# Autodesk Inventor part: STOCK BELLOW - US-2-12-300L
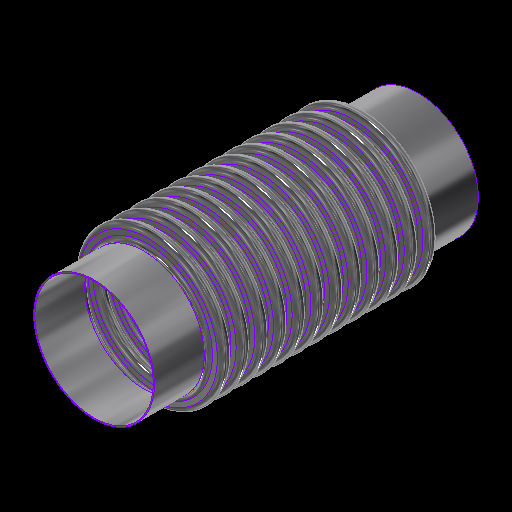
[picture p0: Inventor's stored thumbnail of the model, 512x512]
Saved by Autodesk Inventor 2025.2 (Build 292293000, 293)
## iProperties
Category: 24 GA (0.024 THICK)
RuleStatus: InUse
Created: 2024-01
Part Number: STOCK BELLOW - US-2-12-300L
Project: =STOCK BELLOWS: <Stock Number><SFILL>
Material: ASTM A240-304
Description: =STOCK BELLOWS: <Stock Number>, <SID_> I.D., <SOD_> O.D., <SPLY_> PLY, <Category>, <SNET_CONS> CONS.<PITCH_><STANGENT_> TANGENT<SFILL>
Document SubType Name: Sheet Metal
Designer: GS
Stock Number: U.S-2-12-300L
Surface Area: 1235.64 cm^2
Volume: 37.4488 cm^3
Sheet Metal Rule: Default
Appearance: STAINLESS STEEL
Mass: 301.736 g
Density: 8.05729 g/cm^3
THK: 0.036
ID: 3.500
OD: 4.250
CONS_: 2
PITCH: 0.500
TANGENT: 0.500
BELLOWS_UPSET: 0.000
d79: 1.000
d82: 1.000
d83: 26.000
d84: 24.000
d174: 8
d214: 8
STHK_: 0.024
SID_: 2.375
SOD_: 3.000
SPITCH_: 0.375
STANGENT__: 1.000
SBELLOWS_UPSET_: 0.000
SDIFF_TAN: 1.000
d252: 2
d275: 2
d287: 0.050
d289: 0.500
d290: 0.000
SOD_NECK: 2 7/16
PLY: 1
PSET: 4.178
PBAR: 1.035
COUNTER: 1.500
NET_TUBE: 3.071
CONS: 2
S_CONS: 0
NET_CONS: 2
ID_M: 88.90 mm
OD_M: 107.95 mm
THK_M: 0.91 mm
ID_U: 3.500 in
OD_U: 4.250 in
THK_U: 0.036 in
TANGENT2: 0.500
TAN_TO_TAN: 1.000 in
d80: 2.571
d81: 10
SID: 2.375
SCONS_: 12
SPITCH: 0.250
STANGENT_: 1.000
SBELLOWS_UPSET: 0.000
SNET_CONS: 12
SS_CONS: 0
SCONS: 8
d190: 8
d191: 1
d192: 1
d193: 8
d194: 0
SIZE: 2.00
PRESSURE: 300
d230: 8
STANGENT: 4.000
SPLY_: 1
d233: 8
d234: 0
d263: 2
d265: 1
d268: 2
d269: 0
d286: 2
d288: 1
d291: 2
d292: 0
SREROLL: 0.750
BLETP: 1.000 ul
PRES_Copy: 85
MATTABLE: 20 GA (0.036 THICK)
PART_NUMBER: U.S-2-12-300L
PITCH_: =, <SPITCH_> PITCH,
CFILL: .
SFILL: .
MESH: ,
COMP: 0.48
EXT: 0.24
LAT: 0.27
ANG: 573
ASR: 693
LSR: 462
ANSR: 14
PRES: 300
COMPM: 4.8
EXTM: 2.4
LATM: 2.70
ASRM: 121.365
PRESM: 20.684
LSRM: 80.910
ANSRM: 2.452
TEMPMIN: 20
TEMPMAX: 800
TEMPMINM: -7
TEMPMAXM: 427
WEIGHTM: 0.302
WEIGHT: 0.665
Author: GS
Keywords: 20 GA (0.036 THICK)
Comments: =STOCK BELLOW - <STOCK NUMBER>
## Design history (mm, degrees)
sketch "Sketch2"
  geometry: L1 (0, -177.245)-(0, 562.856) reference; L2 (45.364, 0)-(44.45, 0); L3 (48.082, -2.718)-(50.343, -2.718); L4 (48.082, -3.632)-(50.343, -3.632); L5 (50.343, -9.982)-(48.082, -9.982); L6 (50.343, -9.068)-(48.082, -9.068); L7 (45.364, -12.7)-(44.45, -12.7); L8 (48.082, 0)-(48.082, -12.7); L9 (50.343, -6.35)-(53.975, -6.35); L10 (44.45, 0)-(44.45, -12.7); L11 (20.376, 102.841)-(20.376, 101.926); L12 (58.262, 457.127)-(58.262, 349.177); L13 (58.262, 444.427)-(58.262, 336.477); L14 (93.133, -58.817)-(93.133, -71.517); L15 (118.746, -66.401)-(118.746, -66.401); L16 (50.343, -9.068)-(50.343, -9.982); L17 (48.082, -9.068)-(48.082, -9.982); L18 (48.082, -9.525)-(50.343, -9.525); L19 (53.975, 0)-(53.975, -12.7); L20 (-50.343, -9.068)-(-50.343, -9.982); L21 (-50.343, -2.718)-(-48.082, -2.718); L22 (-50.343, -3.632)-(-48.082, -3.632); L23 (-48.082, -9.068)-(-50.343, -9.068); L24 (-50.343, -9.525)-(-48.082, -9.525); L25 (-48.082, -9.982)-(-50.343, -9.982); L26 (-48.082, -9.068)-(-48.082, -9.982); L27 (-44.45, 0.653)-(-44.45, -12.047); L28 (-48.082, -6.35)-(-44.45, -6.35); L29 (-50.343, 0.653)-(-50.343, -12.7); L30 (-53.061, 0)-(-53.975, 0); L31 (-53.975, 0)-(-53.975, -12.7); L32 (-53.061, -12.7)-(-53.975, -12.7); A1 r 2.718 centre (48.082, 0) between (45.364, 0) and (48.082, -2.718); A2 r 3.632 centre (48.082, 0) between (44.45, 0) and (48.082, -3.632); A3 r 3.632 centre (50.343, -6.35) between (50.343, -9.982) and (50.343, -2.718); A4 r 2.718 centre (50.343, -6.35) between (50.343, -9.068) and (50.343, -3.632); A5 r 2.718 centre (48.082, -12.7) between (48.082, -9.982) and (45.364, -12.7); A6 r 3.632 centre (48.082, -12.7) between (48.082, -9.068) and (44.45, -12.7); A7 r 3.175 centre (50.343, -6.35) between (50.343, -9.525) and (53.518, -6.35); A8 r 3.175 centre (48.082, -12.7) between (48.082, -9.525) and (44.907, -12.7); A9 r 2.718 centre (-50.343, -12.7) between (-50.343, -9.982) and (-53.061, -12.7); A10 r 2.718 centre (-48.082, -6.35) between (-48.082, -9.068) and (-48.082, -3.632); A11 r 3.175 centre (-48.082, -6.35) between (-48.082, -9.525) and (-44.907, -6.35); A12 r 3.632 centre (-48.082, -6.35) between (-48.082, -9.982) and (-48.082, -2.718); A13 r 3.175 centre (-50.343, -12.7) between (-50.343, -9.525) and (-53.518, -12.7); A14 r 3.632 centre (-50.343, -12.7) between (-50.343, -9.068) and (-53.975, -12.7); A15 r 2.718 centre (-50.343, 0) between (-53.061, 0) and (-50.343, -2.718); A16 r 3.632 centre (-50.343, 0) between (-53.975, 0) and (-50.343, -3.632); 10 further points
  constraints: 62 end point, 38 point on circle, 20 tangent, 16 centre point, 12 parallel, 9 midpoint, 7 vertical, 6 coincident, 6 concentric, 6 point on line, 4 equal radius, 4 perpendicular, 3 horizontal, 1 collinear, 1 horizontal alignment, 10 other
  dimensions: "THK" = 0.9144 distance of L11.start L11.end; "ID" = 88.9 distance of L11.end point (20.376, 13.026); "OD" = 107.95 distance of L12.start L12.end; "PITCH" = 12.7 distance of L12.start L13.start; "TANGENT" = 12.7 distance of L14.start L14.end; "BELLOWS_UPSET" = 0 distance of L15.start L15.end; "d43" = 88.9 diameter of L10 L1 (= ID); "d44" = 107.95 diameter of L9.end L1 (= OD); "d45" = 0.9144 distance between parallel lines of L5 L6 (computed from THK, PLY); "d46" = 3.6322 radius of A3 (computed from PITCH, THK, PLY); "UPSET_PITCH" = 12.7 distance of L2.end L7.end (derived); "SIDEWALL_ANGLE" = 360 deg dimension on L3 L9 (derived); "CON_GAP" = 5.4356 distance of point (48.082, -9.068) point (48.082, -3.632) (derived); "TAN1" = 4.98728 dimension on A8 (derived); "TAN2" = 4.98728 dimension on A7 (derived); "LEG1" = 2.2606 distance of L18.start L18.end (derived); "d278" = 0.9144 distance between parallel lines of L25 L23 (derived); "d279" = 3.6322 radius of A12 (derived); "d280" = 12.7 distance of L30.end L31.end (derived); "d281" = 360 deg dimension on L21 L28 (derived); "d282" = 5.4356 distance of point (-50.343, -9.068) point (-50.343, -3.632) (derived); "d283" = 4.98728 dimension on A13 (derived); "d284" = 4.98728 dimension on A11 (derived); "d285" = 2.2606 distance of L24.start L24.end (derived); "d293" = 88.9 diameter of L27 L1 (derived); "d294" = 107.95 diameter of L31 L1 (derived)
  node "Sketch Rectangular Pattern1" dims "d31" = 25.4, "ID" = 88.9
  node "Sketch Rectangular Pattern2" dims "d39" = 25.4, "PITCH" = 12.7
revolve "CONS" stored, may be unused: angle "d48" = 90 deg
node "BELLOW MIDPLANE"
pattern_linear "Rectangular Pattern2" dims "d52" = 12.7 (= UPSET_PITCH)
sketch "Sketch5"
  geometry: C1 r 45.364 at (0, 0) reference; C2 r 44.45 at (0, 0) reference
extrude "TANGENT" new body sketch "Sketch5" distance "d53" = 12.7 (= TANGENT); taper "d54" = 0 deg
revolve "SAMETAN" stored, may be unused: angle "d65" = 90 deg
revolve "DIFFTAN" stored, may be unused: angle "d70" = 90 deg
sketch "Sketch9"
  geometry: L1 (53.319, 0)-(-53.319, 0) reference; L2 (0, -17.78)-(0, 17.78) reference; L3 (38.085, 0)-(-38.085, 0); L4 (38.085, -11.906)-(38.085, 11.906); L5 (25.385, -11.906)-(25.385, 11.906); L6 (13.15, 11.906)-(13.15, -11.906); L7 (-25.385, -11.906)-(-25.385, 11.906); L8 (-38.085, -11.906)-(-38.085, 11.906); L9 (37.291, -11.906)-(37.291, 11.906); L10 (38.085, -11.906)-(37.291, -11.906); L11 (38.085, 11.906)-(37.291, 11.906); L12 (13.546, 11.906)-(12.753, 11.906); L13 (12.753, 11.906)-(12.753, -11.906); L14 (12.753, -11.906)-(13.546, -11.906); L15 (13.546, -11.906)-(13.546, 11.906); L16 (-13.546, 11.906)-(-13.546, -11.906); L17 (-13.15, 11.906)-(-13.15, -11.906); L18 (-13.546, -11.906)-(-12.753, -11.906); L19 (-12.753, -11.906)-(-12.753, 11.906); L20 (-12.753, 11.906)-(-13.546, 11.906); L21 (-38.085, -11.906)-(-37.291, -11.906); L22 (-37.291, -11.906)-(-37.291, 11.906); L23 (-37.291, 11.906)-(-38.085, 11.906); L24 (-38.085, 11.906)-(-38.085, -11.906); L25 (38.085, -0.397)-(-38.085, -0.397); L26 (-38.085, -0.397)-(-38.085, 0.397); L27 (-38.085, 0.397)-(38.085, 0.397); L28 (38.085, 0.397)-(38.085, -0.397); L29 (-38.085, 11.906)-(38.085, 11.906); L30 (38.085, 11.906)-(38.085, 12.7); L31 (38.085, 12.7)-(-38.085, 12.7); L32 (-38.085, 12.7)-(-38.085, 11.906); L33 (38.085, -11.906)-(-38.085, -11.906); L34 (-38.085, -11.906)-(-38.085, -12.7); L35 (-38.085, -12.7)-(38.085, -12.7); L36 (38.085, -12.7)-(38.085, -11.906); 30 further points
  constraints: 68 end point, 13 midpoint, 13 parallel, 8 horizontal, 7 perpendicular, 6 equal length, 3 point on line, 2 vertical, 14 other
  dimensions: "d115" = 23.8125 distance of L4.start L4.end (derived); "d116" = 12.7 distance between parallel lines of L4 L5 (derived); "d117" = 12.23516 distance between parallel lines of L5 L6 (derived); "d125" = 38.53427 distance between parallel lines of L7 L6 (derived); "d127" = 12.7 distance between parallel lines of L8 L7 (derived); "d128" = 24.93516 distance between parallel lines of L6 L4 (derived); "d130" = 76.16943 distance between parallel lines of L8 L4 (derived); "RULER_THK" = 0.79375 distance between parallel lines of L4 L9; "d135" = 0.79375 distance of L13.end L14.end (derived); "d138" = 26.29911 distance of L13.end L16.end (derived); "d143" = 0.79375 distance of L22.end L8.end (derived); "d144" = 0.79375 distance between parallel lines of L27 L25 (derived)
extrude "RULER" join sketch "Sketch9" distance "d149" = 0.79375 (derived); taper "d150" = 0 deg
extrude "BARS" join sketch "Sketch9" distance "d151" = 0.79375 (derived); taper "d152" = 0 deg
pattern_linear "Rectangular Pattern4" dims "d155" = 26.29911 (derived)
sketch "Sketch13"
  geometry: L1 (93.149, -52.467)-(93.149, -77.867); L2 (30.772, 0)-(30.162, 0); L3 (30.772, -9.525)-(30.162, -9.525); L4 (35.414, -7.449)-(32.849, -7.449); L5 (35.414, -6.839)-(32.849, -6.839); L6 (35.414, -4.763)-(38.1, -4.762); L7 (32.849, -2.076)-(35.414, -2.076); L8 (32.849, 0)-(32.849, -9.525); L9 (30.162, 0)-(30.162, -9.525); L10 (58.254, -420.231)-(58.254, -496.431); L11 (58.254, -429.756)-(58.254, -505.956); L12 (58.254, -448.806)-(58.254, -525.006); L13 (58.254, -458.331)-(58.254, -534.531); L14 (58.254, -467.856)-(58.254, -544.056); L15 (58.254, -477.381)-(58.254, -553.581); L16 (58.254, -486.906)-(58.254, -563.106); L17 (58.254, -439.281)-(58.254, -515.481); L18 (20.376, 102.536)-(20.376, 101.926); L19 (32.849, -2.686)-(35.414, -2.686); L20 (0, -696.234)-(0, 235.664) reference; L21 (-23.752, 0)-(142.514, 0) reference; A1 r 2.076 centre (32.849, 0) between (30.772, 0) and (32.849, -2.076); A2 r 2.076 centre (32.849, -9.525) between (32.849, -7.449) and (30.772, -9.525); A3 r 2.686 centre (32.849, -9.525) between (32.849, -6.839) and (30.162, -9.525); A4 r 2.076 centre (35.414, -4.763) between (35.414, -6.839) and (35.414, -2.686); A5 r 2.686 centre (35.414, -4.763) between (35.414, -7.449) and (35.414, -2.076); A6 r 2.686 centre (32.849, 0) between (30.162, 0) and (32.849, -2.686); 6 further points; 1 other entity
  constraints: 38 end point, 15 point on circle, 9 tangent, 6 centre point, 6 parallel, 5 vertical alignment, 4 point on line, 4 vertical, 3 coincident, 3 concentric, 2 collinear, 2 equal radius, 1 horizontal, 1 perpendicular, 23 other
  dimensions: "SBELLOWS_UPSET_" = 0 distance of point (118.762, -66.401) point (118.762, -66.401); "STOTAL_THK_BELLOW__" = 0.6096 distance between parallel lines of L4 L5 (derived); "d224" = 2.68605 radius of A5 (derived); "d225" = 9.525 distance of L2.end L3.end (derived); "SSIDEWALL_ANGLE_" = 360 deg dimension on L7 L6 (derived); "SSCON_GAP_" = 4.1529 distance of point (32.849, -6.839) point (32.849, -2.686) (derived); "d235" = 60.325 diameter of L9 L20 (derived); "d236" = 76.2 diameter of L6.end L20 (derived)
  node "Sketch Rectangular Pattern4" dims "d228" = 25.4
  node "Sketch Rectangular Pattern5" dims "d229" = 25.4
revolve "SBELLOW" stored, may be unused: angle "d197" = 90 deg
pattern_linear "Rectangular Pattern5" dims "d204" = 9.525 (derived)
revolve "STANGENT" stored, may be unused: angle "d240" = 90 deg
revolve "SSAMETAN" stored, may be unused: angle "d241" = 90 deg
revolve "SDIFFTAN" stored, may be unused: angle "d246" = 90 deg
revolve "INVCON" stored, may be unused: angle "d295" = 90 deg
pattern_linear "Rectangular Pattern6" dims "d298" = 12.7 (derived)
revolve "INVTANGENT" stored, may be unused: angle "d302" = 90 deg
revolve "INVSAMETAN" stored, may be unused: angle "d307" = 90 deg
revolve "INVDIFFTAN" stored, may be unused: angle "d312" = 90 deg
sketch "ID BELLOW MOUNT CALC"
  geometry: L1 (44.45, 0)-(38.1, 0); L2 (38.1, 0)-(38.1, 12.7); L3 (38.1, 12.7)-(44.45, 12.7); L4 (44.45, 12.7)-(44.45, 0); L5 (36.513, 12.7)-(35.598, 12.7); L6 (35.598, 12.7)-(35.598, 0); L7 (35.598, 0)-(36.513, 0); L8 (36.513, 0)-(36.513, 12.7); L9 (0, -2.54)-(0, 15.24) reference; L10 (-8.89, 0)-(53.34, 0) reference; 1 further point
  constraints: 16 end point, 5 parallel, 2 collinear, 2 horizontal, 2 perpendicular
  dimensions: "d314" = 12.7 distance of L5.end L6.end (derived); "d315" = 0.9144 distance of L5.start L5.end (derived); "IG" = 1.5875 distance between parallel lines of L2 L8; "PIPE_OD" = 88.9 diameter of L4 L9; "PIPE_WALL" = 6.35 distance of L2.end L3.end; "ID_MT_BELLOW" = 71.1962 diameter of L6 L9 (derived)
revolve "CFILL" stored, may be unused: angle "d320" = 90 deg
pattern_linear "Rectangular Pattern7" dims "d323" = 12.7 (derived)
revolve "SFILL" stored, may be unused: angle "d324" = 90 deg
pattern_linear "Rectangular Pattern8" dims "d327" = 9.525 (derived)
node "STOCK BELLOW MIDPLANE"
node "BELLOW"
sketch "Sketch6"
  geometry: L1 (-12.7, 45.364)-(0, 45.364); L2 (0, 45.364)-(0, 44.45); L3 (0, 44.45)-(-12.7, 44.45); L4 (-12.7, 44.45)-(-12.7, 45.364); L5 (10.16, 0)-(-60.96, 0) reference; L6 (-38.1, -89.422)-(-38.1, 153.44) reference; 1 further point
  constraints: 8 end point, 2 parallel, 1 horizontal, 1 perpendicular
  dimensions: "d61" = 12.7 distance of L2.end L3.end (derived); "d62" = 0.9144 distance of L1.end L2.end (derived); "d63" = 88.9 diameter of L3 L5 (derived); "d64" = 25.4 distance between parallel lines of L4 L6 (derived)
sketch "Sketch12"
  geometry: 1 further point
sketch "Sketch14"
  geometry: L1 (-25.4, 30.772)-(0, 30.772); L2 (0, 30.772)-(0, 30.162); L3 (0, 30.162)-(-25.4, 30.162); L4 (-25.4, 30.162)-(-25.4, 30.772); L5 (5.08, 0)-(-30.48, 0) reference; L6 (0, -8.89)-(0, 53.34) reference; 1 further point
  constraints: 8 end point, 2 parallel, 1 collinear, 1 horizontal, 1 perpendicular
  dimensions: "d237" = 0.6096 distance of L3.end L1.start (derived); "d238" = 60.325 diameter of L3 L5 (derived); "d239" = 25.4 distance of L1.start L1.end (derived); "SOD_NECK" = 61.5442 diameter of L1 L5 (derived)
sketch "Sketch15"
  geometry: L1 (-8.89, 0)-(53.34, 0) reference; L2 (30.163, -114.3)-(30.772, -114.3); L3 (30.772, -114.3)-(30.772, -139.7); L4 (30.772, -139.7)-(30.163, -139.7); L5 (30.163, -139.7)-(30.163, -114.3); L6 (0, -170.18)-(0, 43.18) reference; 1 further point
  constraints: 8 end point, 2 parallel, 1 horizontal, 1 perpendicular
  dimensions: "d205" = 25.4 distance of L4.end L2.start (derived); "d206" = 0.6096 distance of L3.end L4.end (derived); "d207" = 60.325 diameter of L5 L6 (derived); "d208" = 114.3 distance between parallel lines of L1 L2 (derived)
node "TANGENT_"
node "SAME_TAN"
sketch "Sketch8"
  geometry: L1 (45.364, -25.4)-(44.45, -25.4); L2 (44.45, -25.4)-(44.45, -38.1); L3 (44.45, -38.1)-(45.364, -38.1); L4 (45.364, -38.1)-(45.364, -25.4); L5 (0, -48.26)-(0, 22.86) reference; L6 (-89.422, 0)-(153.44, 0) reference; 1 further point
  constraints: 8 end point, 2 parallel, 1 horizontal, 1 perpendicular
  dimensions: "d66" = 88.9 diameter of L2 L5 (derived); "TOTAL_THK_BELLOW" = 0.9144 distance of L2.end L3.end (derived); "d68" = 25.4 distance between parallel lines of L1 L6 (derived); "d69" = 12.7 distance of L1.end L2.end (derived)
node "DIFF_TAN"
node "Sketch Rectangular Pattern3" dims "d138" = 26.29911 (derived), "d141" = 25.4
node "SBELLOW_"
node "STANGENT_"
node "SSAME_TAN"
sketch "Sketch16"
  geometry: L1 (30.772, -114.3)-(30.163, -114.3); L2 (30.163, -114.3)-(30.163, -139.7); L3 (30.163, -139.7)-(30.772, -139.7); L4 (30.772, -139.7)-(30.772, -114.3); L5 (0, -170.18)-(0, 43.18) reference; L6 (-8.89, 0)-(53.34, 0) reference; 1 further point
  constraints: 8 end point, 2 parallel, 1 horizontal, 1 perpendicular
  dimensions: "SDIFF_TAN" = 25.4 distance of L3.end L1.start; "d243" = 0.6096 distance of L2.end L3.end (derived); "d244" = 114.3 distance between parallel lines of L1 L6 (derived); "d245" = 60.325 diameter of L2 L5 (derived)
node "SDIFF_TAN"
body "Solid15"
sketch "Sketch17"
  geometry: L1 (53.975, 12.7)-(53.061, 12.7); L2 (53.061, 12.7)-(53.061, 0); L3 (53.061, 0)-(53.975, 0); L4 (53.975, 0)-(53.975, 12.7); L5 (0, -2.54)-(0, 15.24) reference; L6 (-10.795, 0)-(64.77, 0) reference; 2 further points
  constraints: 8 end point, 2 parallel, 1 horizontal, 1 midpoint, 1 perpendicular, 1 point on line
  dimensions: "INVTANGENT" = 12.7 distance of L3.end L1.start (derived); "d300" = 0.9144 distance of L1.start L1.end (derived); "d301" = 107.95 diameter of L4 L5 (derived)
body "Solid16"
sketch "Sketch18"
  geometry: L1 (53.975, -25.4)-(53.061, -25.4); L2 (53.061, -25.4)-(53.061, -38.1); L3 (53.061, -38.1)-(53.975, -38.1); L4 (53.975, -38.1)-(53.975, -25.4); L5 (-10.795, 0)-(64.77, 0) reference; L6 (0, -48.26)-(0, 22.86) reference; 1 further point
  constraints: 8 end point, 2 parallel, 1 horizontal, 1 perpendicular
  dimensions: "d303" = 25.4 distance between parallel lines of L1 L5 (derived); "d304" = 12.7 distance of L3.end L1.start (derived); "d305" = 0.9144 distance of L2.end L3.end (derived); "d306" = 107.95 diameter of L4 L6 (derived)
body "Solid17"
sketch "Sketch19"
  geometry: L1 (53.975, -25.4)-(53.061, -25.4); L2 (53.061, -25.4)-(53.061, -38.1); L3 (53.061, -38.1)-(53.975, -38.1); L4 (53.975, -38.1)-(53.975, -25.4); L5 (0, -48.26)-(0, 22.86) reference; L6 (-10.795, 0)-(64.77, 0) reference; 1 further point
  constraints: 8 end point, 2 parallel, 1 horizontal, 1 perpendicular
  dimensions: "d308" = 12.7 distance of L1.end L2.end (derived); "d309" = 107.95 diameter of L4 L5 (derived); "d310" = 0.9144 distance of L2.end L3.end (derived); "d311" = 25.4 distance between parallel lines of L1 L6 (derived)
body "Solid18"
body "Solid19"
body "Solid20"
other parameters: "BMPL" = -57.15, "PSET" = 106.1212 (computed from OD, THK, PLY) [user parameter], "PBAR" = 26.29911 (= 0.570796 x PITCH + OD - ID) [user parameter; used in 1 equation term], "COUNTER" = 15 [user parameter], "NET_TUBE" = 77.99823 (computed from CONS_, PBAR, TANGENT) [user parameter], "S_CONS" = 0 [user parameter; used in 1 equation term], "ID_M" = 88.9 (= ID) [user parameter], "OD_M" = 107.95 (= OD) [user parameter], "THK_M" = 0.9144 (= THK) [user parameter], "ID_U" = 88.9 (= ID) [user parameter], "OD_U" = 107.95 (= OD) [user parameter], "THK_U" = 0.9144 (= THK) [user parameter], "D_UNITS" = 0 [user parameter], "TANGENT2" = 12.7 [user parameter], "TAN_TO_TAN" = 25.4 [user parameter], "OD_NECK" = 90.7288 [user parameter], "d79" = 25.4, "d80" = 65.29823 [user parameter], "d82" = 25.4, "d83" = 660.4, "d84" = 609.6, "sa_0" = 4, "FRAME_THK" = 0.79375 [user parameter], "CON_FLAT" = 12.23516 [user parameter], "SID" = 60.325 [user parameter], "SPITCH" = 6.35 [user parameter], "STANGENT_" = 25.4 [user parameter], "SBELLOWS_UPSET" = 0 [user parameter], "SS_CONS" = 0 [user parameter], "STAN_TO_TAN_" = 114.3 [user parameter], "d100" = 0.6096 [user parameter], "d191" = 25.4 [user parameter], "d194" = 0 [user parameter], "STANGENT" = 101.6 [user parameter], "d234" = 0 [user parameter], "SUPSET_PITCH_" = 9.525 [user parameter], "d269" = 0 [user parameter], "d287" = 1.27, "d289" = 12.7, "d290" = 0, "d292" = 0 [user parameter], "Thickness" = 3.048 (derived), "KFactor" = 4.4, "BendRadius" = 3.048 (derived), "BendReliefWidth" = 3.048 (derived), "BendReliefDepth" = 1.524 (derived), "CornerReliefSize" = 12.192 (derived), "SeamGap" = 0.00508, "MinimumRemnant" = 6.096 (derived), "TransitionRadius" = 3.048 (derived), "JacobiRadiusSize" = 3.048 (derived), "GapSize" = 3.048 (derived), "SREROLL" = 19.05 [user parameter], "CUR_STK_PITCH" = 9.525 [user parameter], "d328" = -57.15 (derived), "BLETP" = 1 [user parameter], "ASRM" = 1213.6509 [user parameter], "PRESM" = 206.83949 [user parameter], "LSRM" = 809.1006 [user parameter], "ANSRM" = 24.5182 [user parameter], "TEMPMIN" = 2664.83333 [user parameter], "TEMPMAX" = 6998.16667 [user parameter], "TEMPMINM" = 2664.83333 [user parameter], "TEMPMAXM" = 6998.16667 [user parameter], "WEIGHT" = 3.01736 [user parameter], "WEIGHTM" = 0.00302 [user parameter]
